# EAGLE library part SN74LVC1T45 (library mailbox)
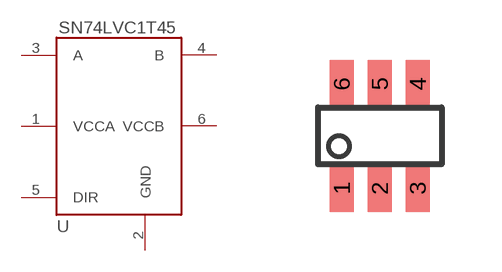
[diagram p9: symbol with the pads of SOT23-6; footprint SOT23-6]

Designator prefix -

## SN74LVC1T45  [SOT23-6]
1  VCCA
2  GND
3  A
4  B
5  DIR
6  VCCB

## Footprint SOT23-6 (pad centres in mm)
Small Outline Transistor, 5 lead
smd 0.6 x 1.2: 1 -0.95,-1.306; 2 0,-1.306; 3 0.95,-1.306; 4 0.95,1.306; 5 0.003,1.306; 6 -0.95,1.306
